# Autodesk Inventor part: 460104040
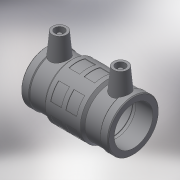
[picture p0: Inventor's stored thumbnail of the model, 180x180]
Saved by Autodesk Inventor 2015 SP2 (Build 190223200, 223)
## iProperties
Created: 2017-06
Part Number: 460104040
Material: Generic
Description: PLASSON LIGHTFIT COUPLER 40
Document SubType Name: Modeling
Designer: KIM
Mass: 89.5427 g
Surface Area: 304.58 cm^2
Volume: 89.5427 cm^3
Density: 1 g/cm^3
Appearance: Default
Author: KIM
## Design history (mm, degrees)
derived "460104.ipt"
feature "Solid1::460104.ipt"
tag "TaggingFeature1"
body "Solid1"
other parameters: "d14" = 17.6296, "d15" = 43, "d16" = 43, "d17" = 39.6, "d19" = 3.52592, "d20" = 168 deg, "d22" = 52.64, "d23" = 56, "d24" = 51.0608, "d25" = 135 deg, "d26" = 36, "d27" = 135 deg, "d29" = 47, "d35" = 15, "d39" = 5 deg, "d44" = 4, "d46" = 14, "d47" = 0, "d52" = 54.88, "d53" = 4.5, "d54" = 4.5, "d55" = 4.5, "d56" = 35 deg, "d58" = 360 deg, "d60" = 8.6, "d61" = 135 deg, "d62" = 31.5, "d63" = 3, "d64" = 0, "L_1" = 43, "D_" = 56, "A_" = 47, "d_2" = 8
